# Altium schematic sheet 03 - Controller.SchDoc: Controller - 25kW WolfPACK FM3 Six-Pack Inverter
size 431 x 279 mm; Date: 07/2023; DocumentNumber: CRD25DA12N-FMC; Revision: 1.1; SheetNumber: 3; SheetTotal: 8; SheetSize: B
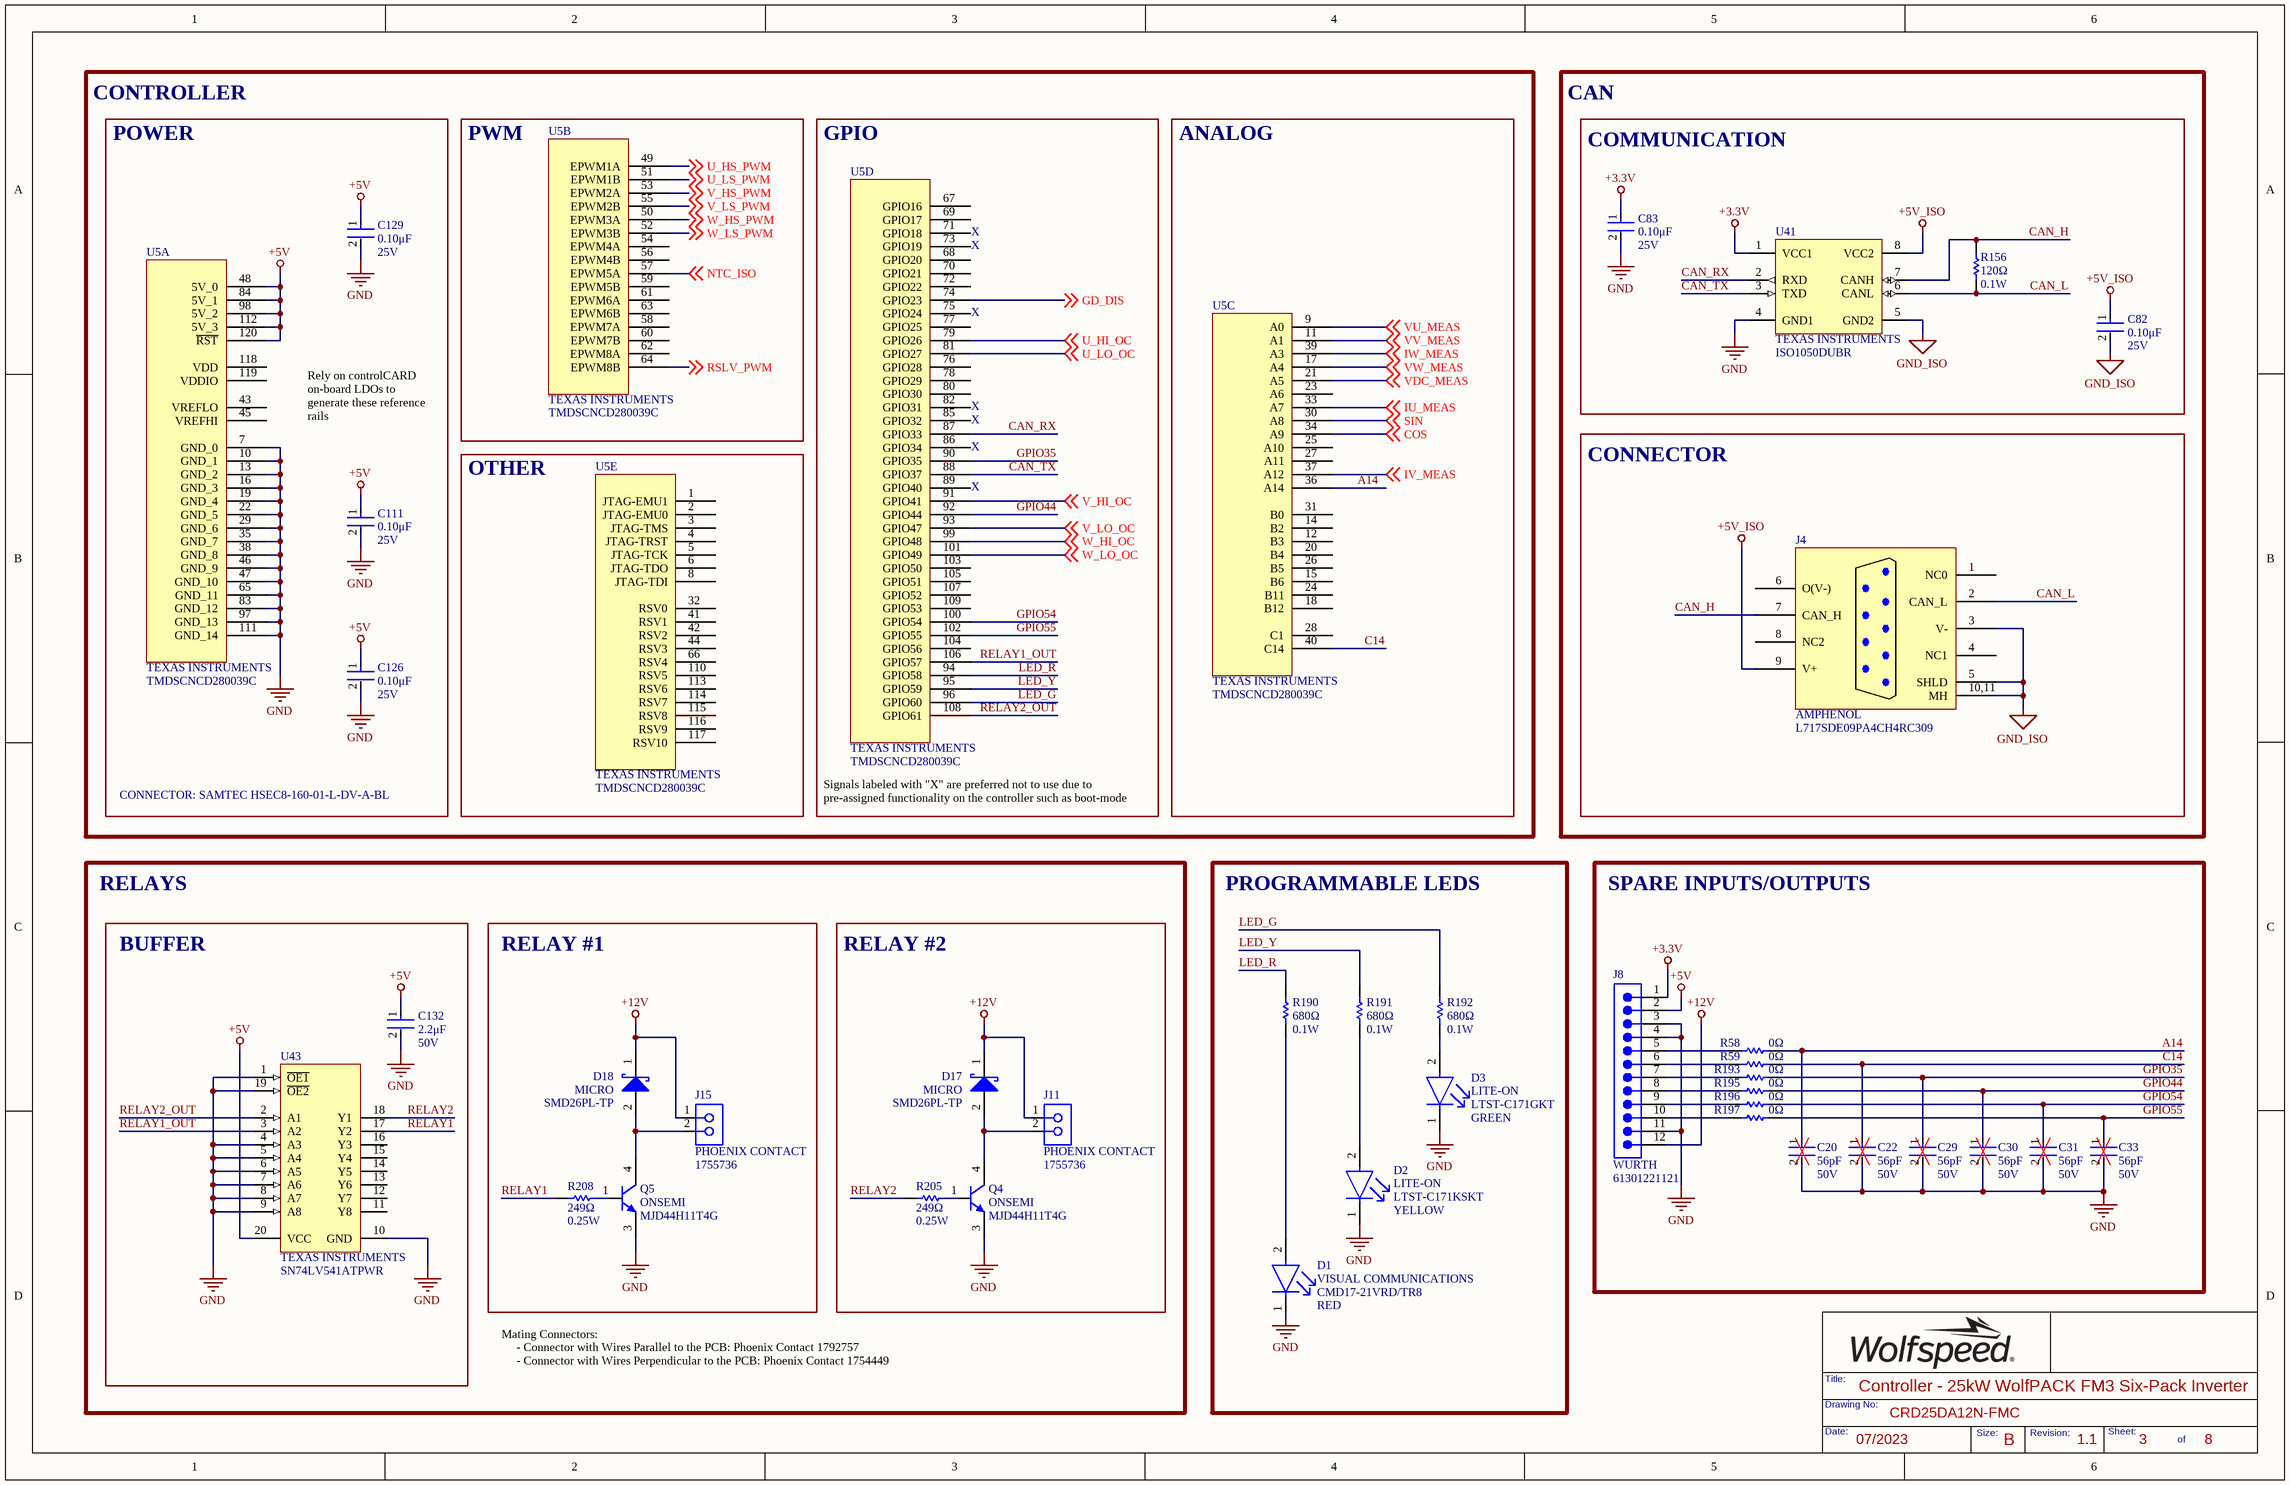
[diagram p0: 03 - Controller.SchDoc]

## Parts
C20  Capacitance: 56pF  Voltage Rating: 50V  [FP-C0603C-CF-IPC_B]  (hidden comment: CL10C560JB8NNNC)
C22  Capacitance: 56pF  Voltage Rating: 50V  [FP-C0603C-CF-IPC_B]  (hidden comment: CL10C560JB8NNNC)
C29  Capacitance: 56pF  Voltage Rating: 50V  [FP-C0603C-CF-IPC_B]  (hidden comment: CL10C560JB8NNNC)
C30  Capacitance: 56pF  Voltage Rating: 50V  [FP-C0603C-CF-IPC_B]  (hidden comment: CL10C560JB8NNNC)
C31  Capacitance: 56pF  Voltage Rating: 50V  [FP-C0603C-CF-IPC_B]  (hidden comment: CL10C560JB8NNNC)
C33  Capacitance: 56pF  Voltage Rating: 50V  [FP-C0603C-CF-IPC_B]  (hidden comment: CL10C560JB8NNNC)
C82  Voltage Rating: 25V  Capacitance: 0.10μF  [FP-C0603C-CF-IPC_B]  (hidden comment: C0603C104K3RACTU)
C83  Voltage Rating: 25V  Capacitance: 0.10μF  [FP-C0603C-CF-IPC_B]  (hidden comment: C0603C104K3RACTU)
C111  Voltage Rating: 25V  Capacitance: 0.10μF  [FP-C0603C-CF-IPC_B]  (hidden comment: C0603C104K3RACTU)
C126  Voltage Rating: 25V  Capacitance: 0.10μF  [FP-C0603C-CF-IPC_B]  (hidden comment: C0603C104K3RACTU)
C129  Voltage Rating: 25V  Capacitance: 0.10μF  [FP-C0603C-CF-IPC_B]  (hidden comment: C0603C104K3RACTU)
C132  Voltage Rating: 50V  Capacitance: 2.2μF  [FP-C0603C-CF-IPC_B]  (hidden comment: GRT188R61H225ME13D)
D1  value RED  Manufacturer: VISUAL COMMUNICATIONS  [FP-LTST-C171GKT-MFG-RED]  (hidden comment: CMD17-21VRD/TR8)
D2  LTST-C171KSKT  value YELLOW  Manufacturer: LITE-ON  [FP-LTST-C171GKT-MFG-YELLOW]
D3  value GREEN  Manufacturer: LITE-ON  [FP-LTST-C171GKT-MFG]  (hidden comment: LTST-C171GKT)
D17  SMD26PL-TP  Manufacturer Print: MICRO  [ONSC-SOD-123FL-2-498-01_V]
D18  SMD26PL-TP  Manufacturer Print: MICRO  [ONSC-SOD-123FL-2-498-01_V]
J4  Manufacturer: AMPHENOL  [L717SDE09PA4CH4RC309]  (hidden comment: L717SDE09PA4CH4RC309)
J8  Manufacturer Print: WURTH  [FP-61301221121-MFG]  (hidden comment: 61301221121)
J11  Manufacturer: PHOENIX CONTACT  [1755736]  (hidden comment: 1755736)
J15  Manufacturer: PHOENIX CONTACT  [1755736]  (hidden comment: 1755736)
Q4  Manufacturer: ONSEMI  [ONSC-DPAK-3-369C-01_V]  (hidden comment: MJD44H11T4G)
Q5  Manufacturer: ONSEMI  [ONSC-DPAK-3-369C-01_V]  (hidden comment: MJD44H11T4G)
R58  Resistance: 0Ω  [FP-MCR03-IPC_B]  (hidden comment: CRCW06030000Z0EB)
R59  Resistance: 0Ω  [FP-MCR03-IPC_B]  (hidden comment: CRCW06030000Z0EB)
R156  Resistance: 120Ω  Max Power Dissipation: 0.1W  [FP-MCR03-IPC_B]  (hidden comment: RC0603JR-07120RL)
R190  Power Rating: 0.1W  Resistance: 680Ω  [FP-MCR03-IPC_B]  (hidden comment: RC0603FR-07680RL)
R191  Power Rating: 0.1W  Resistance: 680Ω  [FP-MCR03-IPC_B]  (hidden comment: RC0603FR-07680RL)
R192  Power Rating: 0.1W  Resistance: 680Ω  [FP-MCR03-IPC_B]  (hidden comment: RC0603FR-07680RL)
R193  Resistance: 0Ω  [FP-MCR03-IPC_B]  (hidden comment: CRCW06030000Z0EB)
R195  Resistance: 0Ω  [FP-MCR03-IPC_B]  (hidden comment: CRCW06030000Z0EB)
R196  Resistance: 0Ω  [FP-MCR03-IPC_B]  (hidden comment: CRCW06030000Z0EB)
R197  Resistance: 0Ω  [FP-MCR03-IPC_B]  (hidden comment: CRCW06030000Z0EB)
R205  Resistance: 249Ω  Power Rating: 0.25W  [FP-MCR18-IPC_A]  (hidden comment: RC1206FR-07249RL)
R208  Resistance: 249Ω  Power Rating: 0.25W  [FP-MCR18-IPC_A]  (hidden comment: RC1206FR-07249RL)
U5  TMDSCNCD280039C  Manufacturer: TEXAS INSTRUMENTS  [TMDSCNCD280039C]  (parts A,B,C,D,E of 5)
U41  ISO1050DUBR  Manufacturer Print: TEXAS INSTRUMENTS  [DUB0008A_M]
U43  Manufacturer: TEXAS INSTRUMENTS  [PW0020A_L]  (hidden comment: SN74LV541ATPWR)

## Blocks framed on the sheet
POWER: C111 C126 C129 U5
PWM: U5
GPIO: U5
ANALOG: U5
COMMUNICATION: C82 C83 R156 U41
CONNECTOR: J4
OTHER: U5
PROGRAMMABLE LEDS: D1-D3 R190-R192
SPARE INPUTS/OUTPUTS: C20 C22 C29-C31 C33 J8 R58 R59 R193 R195-R197
BUFFER: C132 U43
RELAY #1: D18 J15 Q5 R208
RELAY #2: D17 J11 Q4 R205

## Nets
+3.3V: C83.1 J8.1 U41.1(VCC1)
+5V: C111.1 C126.1 C129.1 C132.1 J8.2 U5.48(5V_0) U5.84(5V_1) U5.98(5V_2) U5.112(5V_3) U5.120(~{RST}) U43.20(VCC)
+5V_ISO: C82.1 J4.9(V+) U41.8(VCC2)
+12V: D17.1(K) D18.1(K) J8.12 J11.1 J15.1
GND: C20.2 C22.2 C29.2 C30.2 C31.2 C33.2 C83.2 C111.2 C126.2 C129.2 C132.2 D1.1(C) D2.1(C) D3.1(C) J8.3 J8.4 J8.11 Q4.3(E) Q5.3(E) U5.7(GND_0) U5.10(GND_1) U5.13(GND_2) U5.16(GND_3) U5.19(GND_4) U5.22(GND_5) U5.29(GND_6) U5.35(GND_7) U5.38(GND_8) U5.46(GND_9) U5.47(GND_10) U5.65(GND_11) U5.83(GND_12) U5.97(GND_13) U5.111(GND_14) U41.4(GND1) U43.1(~{OE1}) U43.4(A3) U43.5(A4) U43.6(A5) U43.7(A6) U43.8(A7) U43.9(A8) U43.10(GND) U43.19(~{OE2})
GND_ISO: C82.2 J4.3(V-) J4.5(SHLD) J4.10,11(MH) U41.5(GND2)
A14: C20.1 R58.2 U5.36(A14)
C14: C22.1 R59.2 U5.40(C14)
CAN_H: J4.7(CAN_H) R156.2 U41.7(CANH)
CAN_L: J4.2(CAN_L) R156.1 U41.6(CANL)
CAN_RX: U5.87(GPIO33) U41.2(RXD)
CAN_TX: U5.88(GPIO37) U41.3(TXD)
COS: U5.34(A9) ; off-sheet COS
GD_DIS: U5.74(GPIO23) ; off-sheet GD_DIS
GPIO35: C29.1 R193.2 U5.90(GPIO35)
GPIO44: C30.1 R195.2 U5.92(GPIO44)
GPIO54: C31.1 R196.2 U5.100(GPIO54)
GPIO55: C33.1 R197.2 U5.102(GPIO55)
IU_MEAS: U5.33(A7) ; off-sheet IU_MEAS
IV_MEAS: U5.37(A12) ; off-sheet IV_MEAS
IW_MEAS: U5.39(A3) ; off-sheet IW_MEAS
LED_G: R192.2 U5.96(GPIO60)
LED_R: R190.2 U5.94(GPIO58)
LED_Y: R191.2 U5.95(GPIO59)
NTC_ISO: U5.57(EPWM5A) ; off-sheet NTC_ISO
RELAY1: R208.1 U43.17(Y2)
RELAY1_OUT: U5.106(GPIO57) U43.3(A2)
RELAY2: R205.1 U43.18(Y1)
RELAY2_OUT: U5.108(GPIO61) U43.2(A1)
RSLV_PWM: U5.64(EPWM8B) ; off-sheet RSLV_PWM
SIN: U5.30(A8) ; off-sheet SIN
U_HI_OC: U5.79(GPIO26) ; off-sheet U_HI_OC
U_HS_PWM: U5.49(EPWM1A) ; off-sheet U_HS_PWM
U_LO_OC: U5.81(GPIO27) ; off-sheet U_LO_OC
U_LS_PWM: U5.51(EPWM1B) ; off-sheet U_LS_PWM
V_HI_OC: U5.91(GPIO41) ; off-sheet V_HI_OC
V_HS_PWM: U5.53(EPWM2A) ; off-sheet V_HS_PWM
V_LO_OC: U5.93(GPIO47) ; off-sheet V_LO_OC
V_LS_PWM: U5.55(EPWM2B) ; off-sheet V_LS_PWM
VDC_MEAS: U5.21(A5) ; off-sheet VDC_MEAS
VU_MEAS: U5.9(A0) ; off-sheet VU_MEAS
VV_MEAS: U5.11(A1) ; off-sheet VV_MEAS
VW_MEAS: U5.17(A4) ; off-sheet VW_MEAS
W_HI_OC: U5.99(GPIO48) ; off-sheet W_HI_OC
W_HS_PWM: U5.50(EPWM3A) ; off-sheet W_HS_PWM
W_LO_OC: U5.101(GPIO49) ; off-sheet W_LO_OC
W_LS_PWM: U5.52(EPWM3B) ; off-sheet W_LS_PWM
NetD1_2: D1.2(A) R190.1
NetD2_2: D2.2(A) R191.1
NetD3_2: D3.2(A) R192.1
NetD17_2: D17.2(A) J11.2 Q4.4(C)
NetD18_2: D18.2(A) J15.2 Q5.4(C)
NetJ8_5: J8.5 R58.1
NetJ8_6: J8.6 R59.1
NetJ8_7: J8.7 R193.1
NetJ8_8: J8.8 R195.1
NetJ8_9: J8.9 R196.1
NetJ8_10: J8.10 R197.1
NetQ4_1: Q4.1(B) R205.2
NetQ5_1: Q5.1(B) R208.2

Not connected (* = marked no-connect by the designer): J4 1(NC0) 4(NC1) 6(O(V-)) 8(NC2); U5 1(JTAG-EMU1) 2(JTAG-EMU0) 3(JTAG-TMS) 4(JTAG-TRST) 5(JTAG-TCK) 6(JTAG-TDO) 8(JTAG-TDI) 12(B3) 14(B2) 15(B6) 18(B12) 20(B4) 23(A6) 24(B11) 25(A10) 26(B5) 27(A11) 28(C1) 31(B0) 32(RSV0) 41(RSV1) 42(RSV2) 43(VREFLO) 44(RSV3) 45(VREFHI) 54(EPWM4A) 56(EPWM4B) 58(EPWM7A) 59(EPWM5B) 60(EPWM7B) 61(EPWM6A) 62(EPWM8A) 63(EPWM6B) 66(RSV4) 67(GPIO16) 68(GPIO20) 69(GPIO17) 70(GPIO21) 71(GPIO18) 72(GPIO22) 73(GPIO19) 75(GPIO24) 76(GPIO28) 77(GPIO25) 78(GPIO29) 80(GPIO30) 82(GPIO31) 85(GPIO32) 86(GPIO34) 89(GPIO40) 103(GPIO50) 104(GPIO56) 105(GPIO51) 107(GPIO52) 109(GPIO53) 110(RSV5) 113(RSV6) 114(RSV7) 115(RSV8) 116(RSV9) 117(RSV10) 118(VDD) 119(VDDIO); U43 11(Y8) 12(Y7) 13(Y6) 14(Y5) 15(Y4) 16(Y3)

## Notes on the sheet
- CONTROLLER
- CAN
- (near U5) X
- Rely on controlCARD on-board LDOs to generate these reference rails
- CONNECTOR: SAMTEC HSEC8-160-01-L-DV-A-BL
- Signals labeled with "X" are preferred not to use due to pre-assigned functionality on the controller such as boot-mode selection or on-board LEDs
- RELAYS
- Mating Connectors:
  - Connector with Wires Parallel to the PCB: Phoenix Contact 1792757
  - Connector with Wires Perpendicular to the PCB: Phoenix Contact 1754449

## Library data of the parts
C20 C22 C29-C31 C33 = CL10C560JB8NNNC: CAP CER 56PF 50V C0G/NP0 0603; Manufacturer: SAMSUNG; Material: Ceramic; Tolerance: 5%; Dielectric: C0G; Temperature Coefficient: 30ppm/°C
C82 C83 C111 C126 C129 = CMP-2006-03057-2: CAP CER 0.1UF 25V X7R 0603; Manufacturer: KEMET; Value: 0.10μF; Material: Ceramic; Tolerance: 0.1; Temperature Coefficient: 30ppm/°C; Automotive Grade: Grade 1
C132 = GRT188R61H225ME13D: CAP CER 2.2UF 50V X5R 0603; Manufacturer: MURATA; Tolerance: 20%; Value: 2.2μF
D1 = CMD17-21VRD/TR8: LED RED DIFFUSED 0805 SMD; Power Rating: 100mW; Luminous Intensity: 6mcd; Viewing Angle: 140°; Lens Style: Diffused,Tinted,Rectangular,Colored; Forward Current: 20mA; Forward Voltage: 2V; Wavelength: 640nm; Reverse Voltage (DC): 5V; Number of LEDs: 1
D2 = LTST-C171KSKT: LED YELLOW CLEAR 0805 SMD; Lens Color: Colorless; Number of LEDs: 1; Reverse Voltage: 5V; Viewing Angle: 130°; Lens Style: Diffused,Colorless,Rectangular,Clear; Luminous Intensity: 50mcd; Forward Voltage: 2V; Dominant Wavelength: 587nm; Test Current: 20mA; Wavelength: 588nm; Forward Current: 30mA; Max Power Dissipation: 75mW
D3 = CMP-22017-000007-1: LED GREEN CLEAR CHIP SMD; Luminous Intensity: 12mcd; Lens Color: Colorless; Dominant Wavelength: 569nm; Number of LEDs: 1; Power Dissipation: 100mW; Viewing Angle: 130°; Reverse Voltage: 5V; Test Current: 10mA; Forward Voltage: 2.1V; Wavelength: 585nm; Lens Style: Diffused; Forward Current: 30mA
D17 D18 = SMD26PL-TP: DIODE SCHOTTKY 60V 2A SOD123FL; Manufacturer: MICRO COMMERCIAL; Forward Voltage: 700mV; Max Reverse Current: 500uA; Max Surge Current: 50A; Max Power Dissipation: 1.68W
J4 = L717SDE09PA4CH4RC309: CONN D-SUB PLUG 9POS R/A SLDR; Number of Terminals/Pins: 9; Connector Type: D-Sub,Plug; Voltage Rating: 250V; Current Rating: 5A; Number of Ports: 1; Pitch: 2.74mm
J8 = 61301221121: CONN HEADER VERT 12POS 2.54MM; Manufacturer: WURTH ELEKTRONIK; Number of Positions: 12; Gender: Male; Voltage Rating: 250V; Pitch: 0.1inch
J11 J15 = 1755736: TERM BLOCK HDR 2POS VERT 5.08MM; Content: 250pc(s); Industrial packaging: Yes; Number of contacts: 2
Q4 Q5 = CMP-1046-00010-1: TRANS NPN 80V 8A DPAK; IC Continuous (A): 8; Packing: Tape and Reel
R58 R59 R193 R195-R197 = CRCW06030000Z0EB: RES SMD 0 OHM JUMPER 1/10W 0603; Manufacturer: VISHAY DALE; Manufacturer Part Number: CRCW06030000Z0EBC; Max Power Dissipation: 100mW; Voltage Rating: 75V; Tolerance: 1%; Temperature Coefficient: 100ppm/°C; Value: 0Ω
R156 = RC0603JR-07120RL: RES SMD 120 OHM 5% 1/10W 0603; Manufacturer: YAGEO; Voltage Rating (DC): 50V; Temperature Coefficient: 100ppm/°C; Power Rating: 100mW; Value: 120Ω
R190-R192 = RC0603FR-07680RL: RES 680 OHM 1% 1/10W 0603; Manufacturer: YAGEO; Voltage Rating (DC): 50V; Temperature Coefficient: 100ppm/°C; Max Power Dissipation: 100mW; Value: 680Ω
R205 R208 = RC1206FR-07249RL: RES 249 OHM 1% 1/4W 1206; Manufacturer: YAGEO; Voltage Rating: 200V; Temperature Coefficient: 100ppm/°C; Max Power Dissipation: 250mW; Value: 249Ω
U5 = TMDSCNCD280039C: EVAL BOARD FOR TMS320F280039C
U41 = ISO1050DUBR: IC TXRX/ISO HALF 1/1 8SOP; Rating: Catalog; Eco-Plan: Green (RoHS & no Sb/Br); Isolated: Yes; Drivers Per Package: 1; SubFamily: CAN
U43 = CMP-0440-01163-3: IC BUF NON-INVERT 5.5V 20TSSOP; Bits(#): 8; Voltage(Nom)(V): 5; ICC @ Nom Voltage(Max)(mA): 0.02; VCC(Max)(V): 5.5; Output Type: CMOS; Rating: Catalog; Input Type: TTL; VCC(Min)(V): 4.5; F @ Nom Voltage(Max)(Mhz): 110; tpd @ Nom Voltage(Max)(ns): 7.9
